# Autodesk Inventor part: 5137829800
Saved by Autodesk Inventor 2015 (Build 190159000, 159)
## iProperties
Created: 2020-07
Part Number: 5137829800
Checked By: TraceParts S.A.
Material: Generic
Catalog Web Link: www.traceparts.com
Document SubType Name: Modeling
Designer: TraceParts
Density: 1 g/cm^3
Appearance: Default
Company: TraceParts S.A.
Author: TraceParts
REFERENCE: 5137829800
DESIGN: CVAB-3000/355 N ECOWATT 0,34KW (230V 50/60HZ) N8 - 5137829800
SUPPLIER: Soler & Palau
TraceParts.PartNumber: 10-20122018-119636
TraceParts.PartTitle: CVAB/T-N_ECO
TraceParts.InstanceId: 10-20122018-119636EGX1V3FR1R0X7Z7R3J7NDPJDI
TraceParts.PartStatus: Published
TraceParts.PartVersion: 1.0.2
TRACEPARTS: TRACEPARTS
TraceParts.PartLanguage: en
TraceParts.ClassPath: SOLER_PALAU:10-20122018-119636
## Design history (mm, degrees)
feature "5137829800"
body "Solid1"
